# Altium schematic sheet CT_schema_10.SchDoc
size 147 x 119 mm
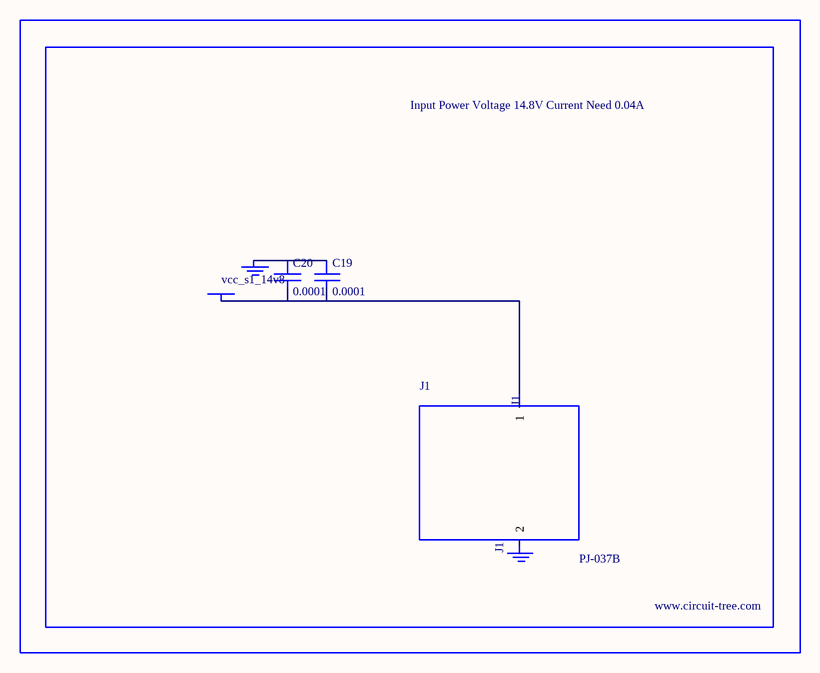
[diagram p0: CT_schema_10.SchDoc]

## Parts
BORDER9  (no value)
C19  0.0001  [EXV-9H]
C20  0.0001  [EXV-9H]
GND_INSTANCE_9_0  (no value)
GND_INSTANCE_9_1  (no value)
J1  PJ-037B  [PJ-037B_PACKAGE]
POWER_INSTANCE_9_0  vcc_s1_14v8

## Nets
NetC19_1: C19.1 C20.1 GND_INSTANCE_9_0.0(GND)
NetC19_2: C19.2 C20.2 J1.1 POWER_INSTANCE_9_0.0(PWR)

Not connected (* = marked no-connect by the designer): GND_INSTANCE_9_1 0(GND); J1 2

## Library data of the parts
BORDER9 = BORDER_PAGE9
C19 C20 = EDK107M035A9HAA
GND_INSTANCE_9_0 GND_INSTANCE_9_1 = GND
POWER_INSTANCE_9_0 = PWR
